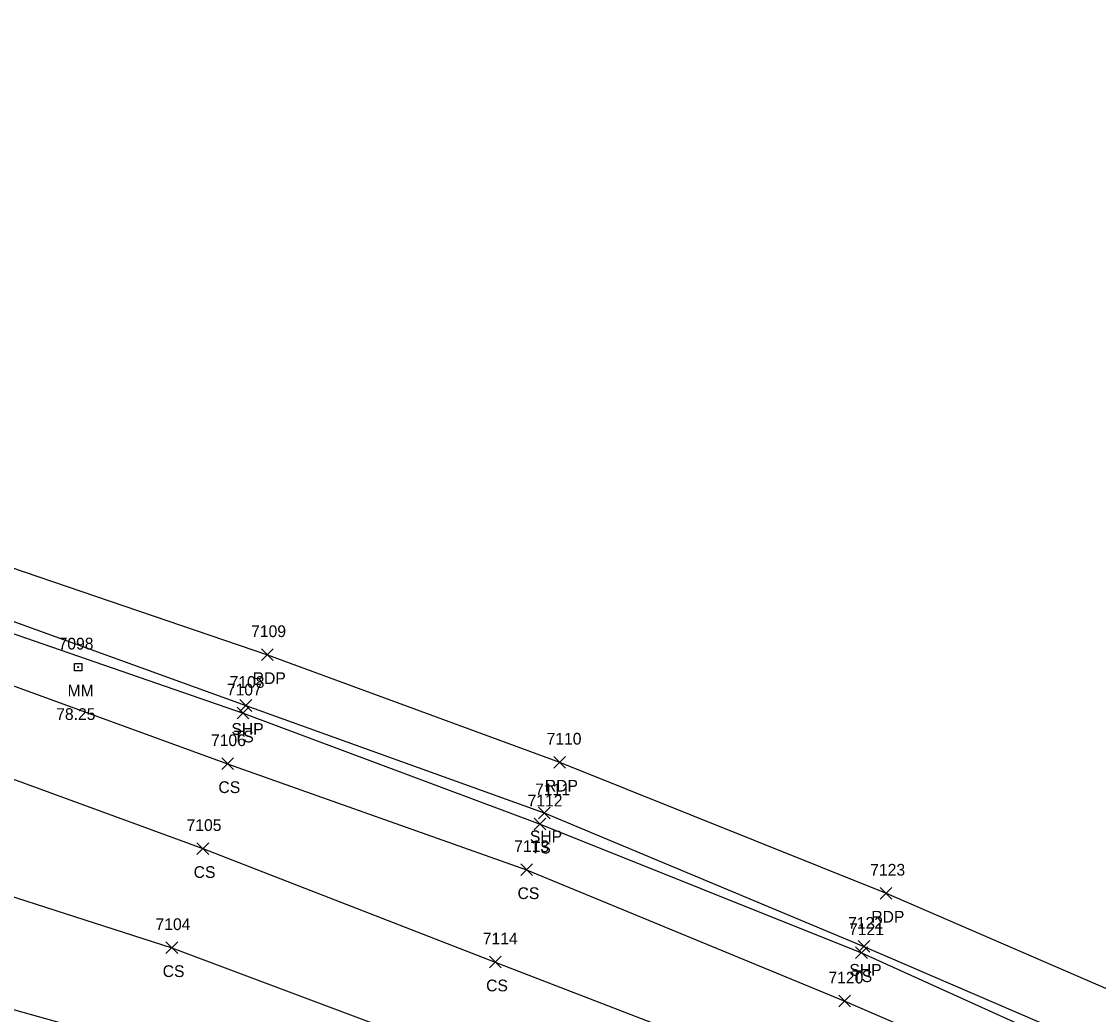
# Model space of a CAD drawing. Extents: x 1505656 to 1508446, y 700805 to 703031.
# Drawn here: x 1507930.5 to 1508114, y 701479.5 to 701648.6 of the extents above; entities that cross this region are included whole.
import ezdxf

# ---------------------------------------------------------------- set-up
doc = ezdxf.new("R2010")
doc.units = 0
for name, color, linetype in [('L_A', 7, 'Continuous'), ('L_I', 7, 'Continuous'), ('L_TIC', 7, 'Continuous'), ('LELB', 7, 'Continuous'), ('LFNC', 7, 'Continuous'), ('P_A', 7, 'Continuous'), ('P_I', 7, 'Continuous'), ('P_TIC', 7, 'Continuous'), ('PET', 7, 'Continuous'), ('PSP', 7, 'Continuous'), ('S_A', 7, 'Continuous'), ('S_C', 7, 'Continuous'), ('S_I', 7, 'Continuous'), ('SRM', 7, 'Continuous')]:
    doc.layers.add(name, color=color, linetype=linetype)

msp = doc.modelspace()

# ---------------------------------------------------------------- linework, layer by layer
at = {"layer": 'L_TIC'}
for points in [[(1507967.27, 701529.82), (1507969.27, 701531.82)], [(1507969.27, 701529.82), (1507967.27, 701531.82)], [(1507964.63, 701521.2), (1507966.63, 701523.2)], [(1507966.63, 701521.2), (1507964.63, 701523.2)], [(1508017.88, 701510.91), (1508019.88, 701512.91)], [(1508019.88, 701510.91), (1508017.88, 701512.91)], [(1507960.41, 701506.74), (1507962.41, 701508.74)], [(1507962.41, 701506.74), (1507960.41, 701508.74)], [(1508015.59, 701503.14), (1508017.59, 701505.14)], [(1508017.59, 701503.14), (1508015.59, 701505.14)], [(1507955.13, 701489.86), (1507957.13, 701491.86)], [(1507957.13, 701489.86), (1507955.13, 701491.86)], [(1508010.25, 701487.42), (1508012.25, 701489.42)], [(1508012.25, 701487.42), (1508010.25, 701489.42)], [(1508072.65, 701489), (1508074.65, 701491)], [(1508074.65, 701489), (1508072.65, 701491)], [(1508069.8, 701480.77), (1508071.8, 701482.77)], [(1508071.8, 701480.77), (1508069.8, 701482.77)]]:
    msp.add_lwpolyline(points, dxfattribs=at)
at = {"layer": 'LELB'}
for points in [[(1507330.99, 701644.33), (1507331.57, 701641.78), (1507371.77, 701640.82), (1507418.46, 701636.99), (1507454.87, 701633.93), (1507504.71, 701630.03), (1507556.91, 701624.43), (1507606.36, 701618.24), (1507661.13, 701610.06), (1507708.24, 701601.04), (1507762.71, 701589.7), (1507814.48, 701577.03), (1507868.53, 701563.07), (1507920.81, 701547.22), (1507968.27, 701530.82), (1508018.88, 701511.91), (1508073.65, 701490), (1508121.33, 701468.38), (1508166.06, 701447.38), (1508217.92, 701421.51), (1508258.5, 701398.83)], [(1507371.82, 701631.2), (1507419.37, 701631.63), (1507454.54, 701624.79), (1507505.05, 701622.5), (1507556.06, 701615.76), (1507605.29, 701610.61), (1507659.37, 701602.95), (1507705.7, 701593), (1507760.19, 701582.5), (1507867, 701555.37), (1507918.17, 701539.42), (1507965.63, 701522.2), (1508016.59, 701504.14), (1508070.8, 701481.77), (1508118.11, 701461.28), (1508164.85, 701439.21), (1508217.28, 701414)], [(1507454.54, 701624.79), (1507504.74, 701612.91), (1507553.31, 701603.43), (1507603.85, 701602.08), (1507655.97, 701590.04), (1507703.48, 701579.9), (1507760.64, 701566.79), (1507809, 701557.31), (1507862.6, 701540.85), (1507913.87, 701525.11), (1507961.41, 701507.74), (1508011.25, 701488.42), (1508064.95, 701467.68), (1508110.8, 701446.82), (1508159.76, 701433), (1508184.08, 701421.84)], [(1507553.31, 701603.43), (1507601.29, 701589.31), (1507651.17, 701577.15), (1507700.01, 701567.77), (1507706.67, 701566.48), (1507755.13, 701548.25), (1507804.73, 701537.71), (1507857.08, 701521.39), (1507908.09, 701506.28), (1507956.13, 701490.86), (1508006.59, 701471.95), (1508058.56, 701454.54), (1508106.68, 701438.49), (1508127.36, 701424.8)]]:
    msp.add_lwpolyline(points, dxfattribs=at)
at = {"layer": 'LFNC'}
msp.add_lwpolyline([(1507703.46, 701543.53), (1507750.96, 701530.99), (1507801.07, 701516.67), (1507850.61, 701502.48), (1507903.46, 701487.51), (1507950.87, 701474.23), (1508002.24, 701459.96), (1508054.23, 701445.25), (1508102.48, 701432.1), (1508087.33, 701416.79), (1508080.06, 701410.17), (1508073.75, 701404.93), (1508071.13, 701402.05), (1508049.1, 701382.67), (1508028.82, 701363.66)], dxfattribs=at)
at = {"layer": 'P_TIC'}
for points in [[(1507971.42, 701539.77), (1507973.42, 701541.77)], [(1507973.42, 701539.77), (1507971.42, 701541.77)], [(1507967.74, 701531.12), (1507969.74, 701533.12)], [(1507969.74, 701531.12), (1507967.74, 701533.12)], [(1508021.2, 701521.45), (1508023.2, 701523.45)], [(1508023.2, 701521.45), (1508021.2, 701523.45)], [(1508018.6, 701512.82), (1508020.6, 701514.82)], [(1508020.6, 701512.82), (1508018.6, 701514.82)], [(1508076.84, 701499.13), (1508078.84, 701501.13)], [(1508078.84, 701499.13), (1508076.84, 701501.13)], [(1508073.06, 701490.08), (1508075.06, 701492.08)], [(1508075.06, 701490.08), (1508073.06, 701492.08)]]:
    msp.add_lwpolyline(points, dxfattribs=at)
at = {"layer": 'PET'}
msp.add_lwpolyline([(1507331.09, 701648.62), (1507371.38, 701647.72), (1507419.18, 701645.9), (1507454.47, 701643.92), (1507505.5, 701639.83), (1507558.24, 701634.71), (1507608.33, 701628.44), (1507662.88, 701620.32), (1507710.96, 701611.67), (1507764.19, 701600.14), (1507816.88, 701587.97), (1507871.99, 701573.08), (1507923.59, 701557.41), (1507972.42, 701540.77), (1508022.2, 701522.45), (1508077.84, 701500.13), (1508126.28, 701479.21), (1508172.23, 701457.76), (1508223.87, 701431.74), (1508273.2, 701405.41), (1508320.32, 701376.47), (1508371.41, 701343.81), (1508408.57, 701317.59), (1508442.85, 701293.88)], dxfattribs=at)
at = {"layer": 'PSP'}
msp.add_lwpolyline([(1507708.42, 701603.34), (1507763.41, 701591.78), (1507815.2, 701579.55), (1507869.54, 701564.45), (1507921.6, 701549.15), (1507968.74, 701532.12), (1508019.6, 701513.82), (1508074.06, 701491.08), (1508122.46, 701470.23), (1508167.01, 701449.38), (1508218.67, 701423.12), (1508267.84, 701395.95), (1508314.49, 701368.02), (1508364.92, 701335.51), (1508402.55, 701308.52), (1508433.77, 701283.19)], dxfattribs=at)
at = {"layer": 'SRM'}
msp.add_lwpolyline([(1507939.55, 701539.27), (1507940.8, 701539.27), (1507940.8, 701538.02), (1507939.55, 701538.02)], close=True, dxfattribs=at)
msp.add_circle((1507940.17, 701538.65), 0.0833, dxfattribs=at)

# ---------------------------------------------------------------- texts
at = {"layer": 'L_A'}
for s, p in [('TS', (1507966.68, 701525.82)), ('CS', (1507964.07, 701517.2)), ('TS', (1508017.29, 701506.91)), ('CS', (1507959.85, 701502.74)), ('CS', (1508015.04, 701499.14)), ('CS', (1507954.57, 701485.86)), ('TS', (1508072.06, 701485)), ('CS', (1508009.69, 701483.42))]:
    msp.add_text(s, height=2, dxfattribs=at).set_placement(p)
at = {"layer": 'L_I'}
for s, p in [('7107', (1507965.5, 701533.82)), ('7106', (1507962.8, 701525.2)), ('7112', (1508016.75, 701514.91)), ('7105', (1507958.64, 701510.74)), ('7113', (1508014.47, 701507.14)), ('7104', (1507953.35, 701493.86)), ('7121', (1508071.53, 701493)), ('7114', (1508009.12, 701491.42)), ('7120', (1508068.02, 701484.77))]:
    msp.add_text(s, height=2, dxfattribs=at).set_placement(p)
at = {"layer": 'P_A'}
for s, p in [('RDP', (1507969.91, 701535.77)), ('SHP', (1507966.28, 701527.12)), ('RDP', (1508019.69, 701517.45)), ('SHP', (1508017.14, 701508.82)), ('RDP', (1508075.32, 701495.13)), ('SHP', (1508071.59, 701486.08))]:
    msp.add_text(s, height=2, dxfattribs=at).set_placement(p)
at = {"layer": 'P_I'}
for s, p in [('7109', (1507969.64, 701543.77)), ('7108', (1507965.97, 701535.12)), ('7110', (1508019.99, 701525.45)), ('7111', (1508018.04, 701516.82)), ('7123', (1508075.14, 701503.13)), ('7122', (1508071.37, 701494.08))]:
    msp.add_text(s, height=2, dxfattribs=at).set_placement(p)
at = {"layer": 'S_A'}
msp.add_text('MM', height=2, dxfattribs=at).set_placement((1507938.36, 701533.65))
at = {"layer": 'S_C'}
msp.add_text('78.25', height=2, dxfattribs=at).set_placement((1507936.42, 701529.65))
at = {"layer": 'S_I'}
msp.add_text('7098', height=2, dxfattribs=at).set_placement((1507936.83, 701541.65))

doc.saveas('drawing.dxf')
